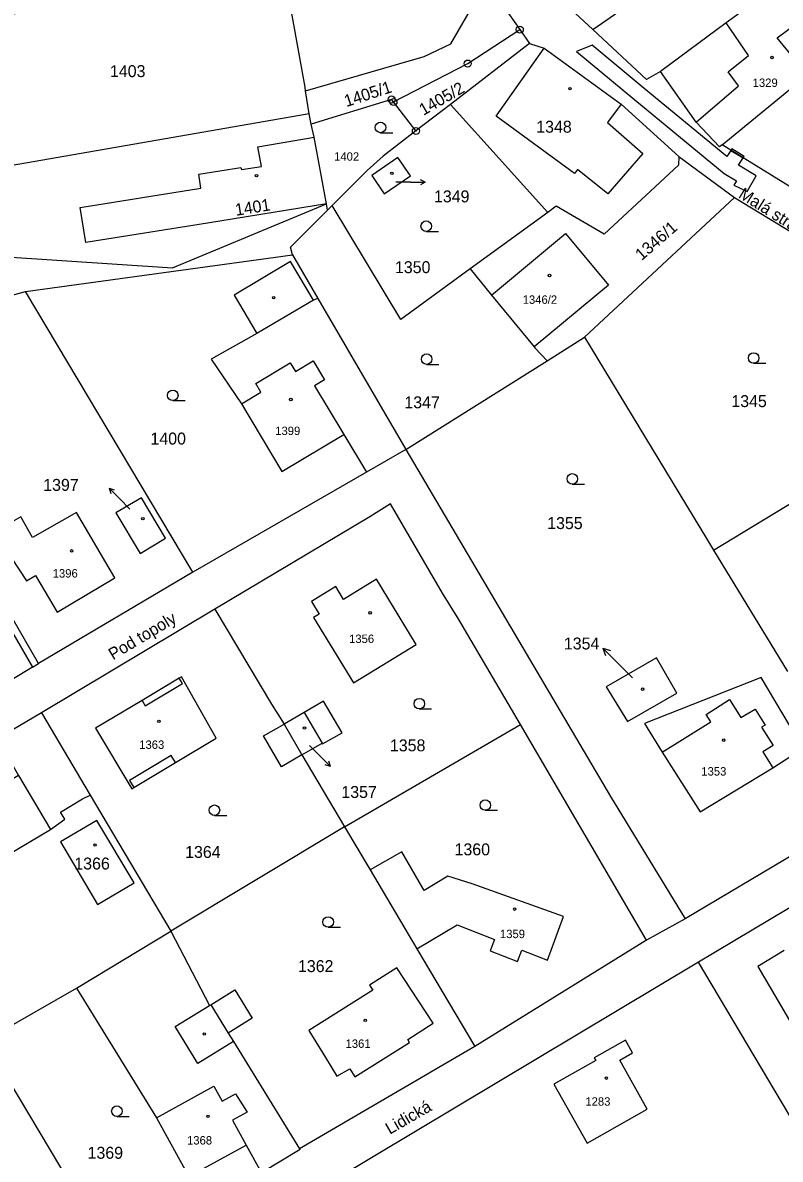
# Model space of a CAD drawing. Extents: x -504988 to -494607, y -1123820 to -1114018.
# Drawn here: x -498111.8 to -498003.8, y -1119261.5 to -1119099.6 of the extents above; entities that cross this region are included whole.
import ezdxf

# ---------------------------------------------------------------- set-up
doc = ezdxf.new("R2010")
doc.units = 0
for name, color, linetype in [('Hranice parcel', 7, 'Continuous'), ('Parcelní čísla', 7, 'Continuous'), ('Pop  PČ popisy', 7, 'Continuous'), ('Vnitřní kresba', 7, 'Continuous'), ('Věcná břemena k části', 7, 'Continuous'), ('Značky bodu BP', 7, 'Continuous'), ('Značky budov', 7, 'Continuous'), ('Značky kultur', 7, 'Continuous')]:
    doc.layers.add(name, color=color, linetype=linetype)

msp = doc.modelspace()

# ---------------------------------------------------------------- linework, layer by layer
at = {"layer": 'Hranice parcel'}
for p, q in [((-498045.7, -1119093.78), (-498040.95, -1119100.58)), ((-498040.95, -1119100.58), (-498039.58, -1119102.55)), ((-498039.58, -1119102.55), (-498050.83, -1119111.22)), ((-498070.95, -1119112.57), (-498071.47, -1119109.28)), ((-498055.76, -1119115.01), (-498058.95, -1119110.88)), ((-498050.83, -1119111.22), (-498055.76, -1119115.01)), ((-498050.83, -1119111.22), (-498036.98, -1119126.61)), ((-498070.66, -1119114.02), (-498070.95, -1119112.57)), ((-497998.68, -1119125.28), (-498012.13, -1119116.99)), ((-498018.31, -1119118.66), (-498010.34, -1119124.5)), ((-498010.34, -1119124.5), (-498031.71, -1119144.39)), ((-498068.34, -1119126.3), (-498068.51, -1119125.4)), ((-498067.67, -1119125.63), (-498068.34, -1119126.3)), ((-498036.98, -1119126.61), (-498048.03, -1119134.66)), ((-498111.4, -1119137.86), (-498073.34, -1119132.64)), ((-498073.34, -1119132.64), (-498069.71, -1119138.88)), ((-498048.03, -1119134.66), (-498044.97, -1119138.39)), ((-498136.33, -1119144.7), (-498111.4, -1119137.86)), ((-498087.55, -1119177.87), (-498111.4, -1119137.86)), ((-498069.71, -1119138.88), (-498057.17, -1119160.39)), ((-498044.97, -1119138.39), (-498038.91, -1119145.75)), ((-498037.03, -1119147.73), (-498031.71, -1119144.39)), ((-498057.17, -1119160.39), (-498037.03, -1119147.73)), ((-498057.17, -1119160.39), (-498062.8, -1119163.63)), ((-498062.8, -1119163.63), (-498087.55, -1119177.87)), ((-498013.33, -1119174.7), (-497996.1, -1119164.22)), ((-498013.33, -1119174.7), (-498002.82, -1119191.98)), ((-498084.4, -1119183.14), (-498109.12, -1119197.88)), ((-498109.12, -1119197.88), (-498115.41, -1119201.58)), ((-498109.12, -1119197.88), (-498102.16, -1119209.6)), ((-498074.54, -1119199.48), (-498071.99, -1119203.88)), ((-498065.91, -1119214.11), (-498040.86, -1119199.56)), ((-498022.92, -1119230.27), (-498040.86, -1119199.56)), ((-498071.99, -1119203.88), (-498065.91, -1119214.11)), ((-497969.63, -1119205.93), (-498015.49, -1119233.41)), ((-498102.16, -1119209.6), (-498090.66, -1119228.96)), ((-497990.95, -1119211.51), (-498017.38, -1119227.24)), ((-498065.91, -1119214.11), (-498090.66, -1119228.96)), ((-498065.91, -1119214.11), (-498062.26, -1119220.26)), ((-498057.77, -1119217.67), (-498062.26, -1119220.26)), ((-498062.26, -1119220.26), (-498055.6, -1119231.5)), ((-498017.38, -1119227.24), (-498022.92, -1119230.27)), ((-498104.11, -1119237.11), (-498090.66, -1119228.96)), ((-498022.92, -1119230.27), (-498047.36, -1119245.4)), ((-498055.6, -1119231.5), (-498047.36, -1119245.4)), ((-498015.49, -1119233.41), (-498067.41, -1119264.46)), ((-498116.93, -1119244.45), (-498104.11, -1119237.11)), ((-498117.19, -1119244.61), (-498098.47, -1119275.83)), ((-498047.36, -1119245.4), (-498072.32, -1119260))]:
    msp.add_line(p, q, dxfattribs=at)
for points in [[(-498030.53, -1119100.54), (-498039.34, -1119092.4), (-498046.56, -1119069.43)], [(-498030.53, -1119100.54), (-498018.03, -1119091.86), (-498003.97, -1119085.2)], [(-498071.47, -1119109.28), (-498071.55, -1119108.79), (-498073.34, -1119098.8), (-498075.74, -1119086.77), (-498132.3, -1119104.31), (-498131.11, -1119113.44)], [(-498071.47, -1119109.28), (-498054.58, -1119104.39), (-498050.79, -1119102.58), (-498045.7, -1119093.78)], [(-498012.13, -1119116.99), (-497999.97, -1119107), (-498004.3, -1119101.73), (-498001.13, -1119099.4), (-498002.9, -1119096.92), (-498003.95, -1119097.55), (-498005.62, -1119095.27), (-498011.54, -1119099.6), (-498020.88, -1119106.56)], [(-498058.95, -1119110.88), (-498048.37, -1119105.41), (-498040.95, -1119100.58)], [(-498020.88, -1119106.56), (-498022.92, -1119107.67), (-498030.53, -1119100.54)], [(-498039.58, -1119102.55), (-498037.48, -1119103.2), (-498026.52, -1119111.17), (-498018.31, -1119118.66)], [(-498012.13, -1119116.99), (-498012.49, -1119117.29), (-498015.82, -1119113.75), (-498020.88, -1119106.56)], [(-498058.95, -1119110.88), (-498059.22, -1119110.53), (-498070.66, -1119114.02)], [(-498070.95, -1119112.57), (-498117.71, -1119120.69), (-498115.44, -1119133.16)], [(-498068.51, -1119125.4), (-498070.27, -1119115.9), (-498070.66, -1119114.02)], [(-498055.76, -1119115.01), (-498060.43, -1119118.6), (-498062.68, -1119120.64), (-498067.67, -1119125.63)], [(-498060.27, -1119123.96), (-498056.53, -1119121.42), (-498058.31, -1119118.81), (-498062.04, -1119121.36), (-498060.27, -1119123.96)], [(-498018.31, -1119118.66), (-498018.36, -1119119.9), (-498028.93, -1119129.72), (-498035.79, -1119125.74), (-498036.98, -1119126.61)], [(-498010.34, -1119124.5), (-497982.64, -1119141.32), (-497971.78, -1119148.38)], [(-498114.09, -1119132.94), (-498090.42, -1119134.5), (-498068.51, -1119125.4)], [(-498073.34, -1119132.64), (-498073.62, -1119131.57), (-498068.34, -1119126.3)], [(-498048.03, -1119134.66), (-498057.89, -1119141.84), (-498067.67, -1119125.63)], [(-498044.97, -1119138.39), (-498034.46, -1119129.61), (-498028.3, -1119136.96), (-498038.91, -1119145.75)], [(-498069.71, -1119138.88), (-498070.35, -1119139.09), (-498073.61, -1119133.62), (-498081.66, -1119138.42), (-498078.41, -1119143.88), (-498084.92, -1119147.52), (-498080.62, -1119153.88), (-498074.84, -1119163.53), (-498066.02, -1119158.25), (-498062.8, -1119163.63)], [(-498087.55, -1119177.87), (-498109.51, -1119190.84), (-498122.93, -1119167.67), (-498136.33, -1119144.7)], [(-498031.71, -1119144.39), (-498014.37, -1119173.04), (-498013.33, -1119174.7)], [(-498137.28, -1119144.99), (-498110.37, -1119191.37), (-498115.64, -1119194.57), (-498135.6, -1119206.51)], [(-498038.91, -1119145.75), (-498038.8, -1119145.89), (-498037.03, -1119147.73)], [(-498057.17, -1119160.39), (-498028.04, -1119209.78), (-498017.38, -1119227.24)], [(-498095.07, -1119175.18), (-498091.44, -1119173.02), (-498094.87, -1119167.25), (-498098.51, -1119169.41), (-498095.07, -1119175.18)], [(-498040.86, -1119199.56), (-498049.65, -1119184.59), (-498051.95, -1119180.83), (-498059.39, -1119168.13), (-498062.3, -1119169.96), (-498084.4, -1119183.14)], [(-498114.25, -1119176.23), (-498113.43, -1119175.76), (-498111.24, -1119179.09), (-498109.97, -1119178.33), (-498106.89, -1119183.53), (-498098.66, -1119178.66), (-498104.13, -1119169.37), (-498110.38, -1119172.93), (-498112.07, -1119169.96), (-498116.41, -1119172.43), (-498114.25, -1119176.23)], [(-498066.07, -1119181.72), (-498067.18, -1119179.91), (-498070.64, -1119182.05), (-498069.55, -1119183.85), (-498070.34, -1119184.33), (-498064.66, -1119193.63), (-498055.7, -1119188.16), (-498061.38, -1119178.86), (-498066.07, -1119181.72)], [(-498084.4, -1119183.14), (-498076.31, -1119196.64), (-498074.54, -1119199.48)], [(-498028.64, -1119194.19), (-498025.6, -1119199.1), (-498018.58, -1119195.08), (-498021.46, -1119190.05), (-498028.64, -1119194.19)], [(-498090.02, -1119204.96), (-498084.23, -1119201.49), (-498089.16, -1119192.78), (-498089.47, -1119192.96), (-498094.78, -1119196.13), (-498101.39, -1119200.07), (-498096.25, -1119208.7), (-498095.95, -1119208.52), (-498090.02, -1119204.96)], [(-498020.66, -1119203.5), (-498015.27, -1119212), (-498004.9, -1119205.7), (-498000.57, -1119202.94), (-498006.55, -1119192.83), (-498023.2, -1119199.42), (-498020.66, -1119203.5)], [(-498071.99, -1119203.88), (-498069.12, -1119202.21), (-498069.05, -1119202.32), (-498066.28, -1119200.71), (-498068.92, -1119196.2), (-498071.68, -1119197.82), (-498074.54, -1119199.48)], [(-498115.41, -1119201.58), (-498112.37, -1119206.82), (-498124.35, -1119213.92), (-498119.8, -1119221.59), (-498107.82, -1119214.5), (-498105.78, -1119213.05), (-498106.4, -1119212.03), (-498103.25, -1119210.13), (-498102.16, -1119209.6)], [(-498101.2, -1119213.23), (-498106.41, -1119216.28), (-498101.14, -1119225.18), (-498095.92, -1119222.09), (-498101.2, -1119213.23)], [(-498051.21, -1119221.14), (-498054.56, -1119223.19), (-498057.77, -1119217.67)], [(-498055.6, -1119231.5), (-498049.9, -1119228.1), (-498044.55, -1119230.18), (-498045.16, -1119231.76), (-498041.27, -1119233.31), (-498040.64, -1119231.69), (-498037.01, -1119233.11), (-498034.71, -1119226.89), (-498047.74, -1119222.24), (-498051.21, -1119221.14)], [(-498090.66, -1119228.96), (-498085.18, -1119239.58), (-498084.97, -1119239.45), (-498082.49, -1119243.5), (-498081.75, -1119244.69), (-498072.32, -1119260)], [(-498003.28, -1119231.73), (-498007.05, -1119234), (-497999.76, -1119246.39), (-497998.25, -1119245.51), (-497995.56, -1119250.06), (-497992, -1119248.03), (-497994.69, -1119243.42), (-497992.88, -1119242.37), (-497993.71, -1119240.91), (-497989.62, -1119238.45), (-497994.74, -1119229.75), (-497996.92, -1119230.9), (-497997.94, -1119228.95), (-497999.45, -1119229.42)], [(-497999.46, -1119260.4), (-498001.57, -1119256.8), (-498015.49, -1119233.41)], [(-498053.32, -1119242.1), (-498058.47, -1119234.19), (-498062.35, -1119236.67)], [(-498062.35, -1119236.67), (-498061.89, -1119237.39), (-498071.03, -1119243.15), (-498068.62, -1119246.99), (-498067, -1119249.65), (-498065.19, -1119248.58), (-498064.46, -1119249.74), (-498056.65, -1119244.82), (-498056.9, -1119244.43), (-498053.32, -1119242.1)], [(-498104.11, -1119237.11), (-498092.72, -1119255.56), (-498088.11, -1119263.94), (-498079.94, -1119259.45), (-498077.76, -1119263.4)], [(-498024.87, -1119246.32), (-498025.89, -1119244.5), (-498030.35, -1119247), (-498030.11, -1119247.42), (-498036.09, -1119250.78), (-498031.36, -1119259.18), (-498022.79, -1119254.35), (-498026.72, -1119247.36), (-498024.87, -1119246.32)], [(-498072.32, -1119260), (-498072.26, -1119260.1), (-498077.76, -1119263.4)]]:
    msp.add_lwpolyline(points, dxfattribs=at)
at = {"layer": 'Pop  PČ popisy'}
for p, q in [((-498054.42, -1119122.32), (-498055.12, -1119121.97)), ((-498056.52, -1119122.32), (-498058.62, -1119122.32)), ((-498056.52, -1119122.32), (-498054.42, -1119122.32)), ((-498054.42, -1119122.32), (-498055.12, -1119122.67)), ((-498097.99, -1119167.37), (-498099.48, -1119165.89)), ((-498099.48, -1119165.89), (-498098.73, -1119166.13)), ((-498099.48, -1119165.89), (-498099.23, -1119166.63)), ((-498096.51, -1119168.86), (-498097.99, -1119167.37)), ((-498026.99, -1119190.79), (-498029.11, -1119188.67)), ((-498029.11, -1119188.67), (-498028.05, -1119189.02)), ((-498029.11, -1119188.67), (-498028.76, -1119189.73)), ((-498024.87, -1119192.92), (-498026.99, -1119190.79)), ((-498070.91, -1119202.56), (-498069.42, -1119204.04)), ((-498069.42, -1119204.04), (-498067.93, -1119205.53)), ((-498067.93, -1119205.53), (-498068.68, -1119205.28)), ((-498067.93, -1119205.53), (-498068.18, -1119204.78))]:
    msp.add_line(p, q, dxfattribs=at)
at = {"layer": 'Vnitřní kresba'}
for p, q in [((-498008.35, -1119104.26), (-498011.54, -1119099.6)), ((-498044.32, -1119112.91), (-498037.48, -1119103.2)), ((-498011.28, -1119106.61), (-498008.35, -1119104.26)), ((-498009.78, -1119108.6), (-498011.28, -1119106.61)), ((-498015.82, -1119113.75), (-498009.78, -1119108.6)), ((-498026.52, -1119111.17), (-498028.44, -1119113.81)), ((-498033.15, -1119121.06), (-498044.32, -1119112.91)), ((-498028.44, -1119113.81), (-498023.41, -1119118.2)), ((-498078.28, -1119117.29), (-498070.27, -1119115.9)), ((-498077.78, -1119120.06), (-498078.28, -1119117.29)), ((-498023.41, -1119118.2), (-498028.41, -1119123.96)), ((-498086.71, -1119121.15), (-498080.68, -1119120.22)), ((-498080.68, -1119120.22), (-498080.63, -1119120.5)), ((-498080.63, -1119120.5), (-498077.78, -1119120.06)), ((-498086.4, -1119123.14), (-498086.71, -1119121.15)), ((-498032.74, -1119120.51), (-498033.15, -1119121.06)), ((-498028.41, -1119123.96), (-498032.74, -1119120.51)), ((-498103.58, -1119125.91), (-498086.4, -1119123.14)), ((-498102.77, -1119130.91), (-498103.58, -1119125.91)), ((-498068.51, -1119125.4), (-498085.44, -1119128.13)), ((-498085.44, -1119128.13), (-498102.77, -1119130.91)), ((-498070.35, -1119139.09), (-498078.41, -1119143.88)), ((-498072.91, -1119149.27), (-498070.39, -1119147.76)), ((-498070.39, -1119147.76), (-498068.78, -1119150.45)), ((-498078.58, -1119150.98), (-498073.65, -1119148.03)), ((-498073.65, -1119148.03), (-498072.91, -1119149.27)), ((-498077.84, -1119152.22), (-498078.58, -1119150.98)), ((-498068.78, -1119150.45), (-498070.19, -1119151.29)), ((-498080.62, -1119153.88), (-498077.84, -1119152.22)), ((-498070.19, -1119151.29), (-498066.02, -1119158.25)), ((-498110.37, -1119191.37), (-498109.51, -1119190.84)), ((-498089.01, -1119193.73), (-498089.47, -1119192.96)), ((-498094.32, -1119196.9), (-498089.01, -1119193.73)), ((-498094.78, -1119196.13), (-498094.32, -1119196.9)), ((-498014.41, -1119198.1), (-498011.05, -1119196)), ((-498011.05, -1119196), (-498009.44, -1119198.57)), ((-498071.68, -1119197.82), (-498069.12, -1119202.21)), ((-498013.75, -1119199.16), (-498014.41, -1119198.1)), ((-498009.44, -1119198.57), (-498007.41, -1119197.36)), ((-498007.41, -1119197.36), (-498006.01, -1119199.65)), ((-498077.45, -1119201.17), (-498074.54, -1119199.48)), ((-498020.66, -1119203.5), (-498013.75, -1119199.16)), ((-498006.01, -1119199.65), (-498006.49, -1119199.93)), ((-498074.9, -1119205.57), (-498077.45, -1119201.17)), ((-498006.49, -1119199.93), (-498004.84, -1119202.56)), ((-498004.84, -1119202.56), (-498006.33, -1119203.45)), ((-498090.62, -1119203.96), (-498096.55, -1119207.51)), ((-498090.02, -1119204.96), (-498090.62, -1119203.96)), ((-498071.99, -1119203.88), (-498074.9, -1119205.57)), ((-498006.33, -1119203.45), (-498004.9, -1119205.7)), ((-498112.37, -1119206.82), (-498107.82, -1119214.5)), ((-498096.55, -1119207.51), (-498095.95, -1119208.52)), ((-498084.97, -1119239.45), (-498081.55, -1119237.35)), ((-498081.55, -1119237.35), (-498079.07, -1119241.38)), ((-498090.05, -1119242.57), (-498085.18, -1119239.58)), ((-498079.07, -1119241.38), (-498082.49, -1119243.5)), ((-498086.83, -1119247.81), (-498090.05, -1119242.57)), ((-498081.75, -1119244.69), (-498086.83, -1119247.81)), ((-498092.72, -1119255.56), (-498084.55, -1119251.07)), ((-498084.55, -1119251.07), (-498083.38, -1119253.2)), ((-498083.38, -1119253.2), (-498081.48, -1119252.15)), ((-498081.48, -1119252.15), (-498079.81, -1119254.77)), ((-498079.81, -1119254.77), (-498081.88, -1119255.91)), ((-498081.88, -1119255.91), (-498079.94, -1119259.45))]:
    msp.add_line(p, q, dxfattribs=at)
at = {"layer": 'Věcná břemena k části'}
for points in [[(-498024.54, -1119110.59), (-498011.81, -1119121.06), (-498010.09, -1119122.12), (-498010.43, -1119122.75), (-498008.54, -1119123.63), (-498007.28, -1119121.39), (-498009.78, -1119119.86), (-498009.14, -1119118.84), (-498010.87, -1119117.77), (-498011.43, -1119118.67), (-498023.22, -1119108.97), (-498030.62, -1119102.81), (-498032.85, -1119103.67)], [(-498010.87, -1119117.77), (-498009.14, -1119118.84), (-498009, -1119118.63), (-498010.73, -1119117.55)]]:
    msp.add_lwpolyline(points, close=True, dxfattribs=at)
at = {"layer": 'Značky bodu BP'}
for centre, radius in [((-498040.95, -1119100.58), 0.5), ((-498040.95, -1119100.58), 0.0303), ((-498048.37, -1119105.41), 0.5), ((-498048.37, -1119105.41), 0.0303), ((-498059.22, -1119110.53), 0.5), ((-498058.95, -1119110.88), 0.5), ((-498059.22, -1119110.53), 0.0303), ((-498058.95, -1119110.88), 0.0303), ((-498055.76, -1119115.01), 0.5), ((-498055.76, -1119115.01), 0.0303)]:
    msp.add_circle(centre, radius, dxfattribs=at)
at = {"layer": 'Značky budov'}
for centre in [(-498005.03, -1119104.55), (-498033.79, -1119108.98), (-498078.47, -1119121.38), (-498059.18, -1119121.05), (-498036.72, -1119135.6), (-498076.01, -1119138.75), (-498073.58, -1119153.26), (-498094.67, -1119170.24), (-498104.81, -1119174.82), (-498062.28, -1119183.64), (-498023.45, -1119194.51), (-498092.38, -1119199.09), (-498071.63, -1119200.05), (-498011.89, -1119201.78), (-498101.47, -1119216.72), (-498041.69, -1119225.84), (-498062.98, -1119241.67), (-498085.91, -1119243.63), (-498028.61, -1119249.91), (-498085.37, -1119255.34)]:
    msp.add_circle(centre, 0.175, dxfattribs=at)
at = {"layer": 'Značky kultur'}
for p, q in [((-498060.8, -1119115.26), (-498059.05, -1119115.26)), ((-498054.28, -1119129.32), (-498052.53, -1119129.32)), ((-498054.22, -1119148.26), (-498052.47, -1119148.26)), ((-498007.63, -1119148.09), (-498005.88, -1119148.09)), ((-498090.4, -1119153.42), (-498088.65, -1119153.42)), ((-498033.47, -1119165.31), (-498031.72, -1119165.31)), ((-498055.27, -1119197.33), (-498053.52, -1119197.33)), ((-498084.46, -1119212.51), (-498082.71, -1119212.51)), ((-498045.87, -1119211.77), (-498044.12, -1119211.77)), ((-498068.26, -1119228.43), (-498066.51, -1119228.43)), ((-498098.36, -1119255.37), (-498096.61, -1119255.37))]:
    msp.add_line(p, q, dxfattribs=at)
for centre in [(-498060.8, -1119114.51), (-498054.28, -1119128.57), (-498054.22, -1119147.51), (-498007.63, -1119147.34), (-498090.4, -1119152.67), (-498033.47, -1119164.56), (-498055.27, -1119196.58), (-498084.46, -1119211.76), (-498045.87, -1119211.02), (-498068.26, -1119227.68), (-498098.36, -1119254.62)]:
    msp.add_circle(centre, 0.75, dxfattribs=at)

# ---------------------------------------------------------------- texts
at = {"layer": 'Parcelní čísla'}
for s, height, p in [('1403', 1.7, (-498099.35, -1119107.34)), ('1329', 1.2, (-498007.77, -1119108.74)), ('1348', 1.7, (-498038.61, -1119115.26)), ('1402', 1.2, (-498067.41, -1119119.25)), ('1349', 1.7, (-498053.18, -1119125.18)), ('1350', 1.7, (-498058.74, -1119135.26)), ('1346/2', 1.2, (-498040.54, -1119139.63)), ('1347', 1.7, (-498057.4, -1119154.51)), ('1345', 1.7, (-498010.81, -1119154.34)), ('1399', 1.2, (-498075.8, -1119158.32)), ('1400', 1.7, (-498093.58, -1119159.67)), ('1397', 1.7, (-498108.86, -1119166.27)), ('1355', 1.7, (-498037.05, -1119171.71)), ('1396', 1.2, (-498107.51, -1119178.62)), ('1356', 1.2, (-498065.28, -1119187.94)), ('1354', 1.7, (-498034.67, -1119188.86)), ('1363', 1.2, (-498095.18, -1119203.02)), ('1358', 1.7, (-498059.46, -1119203.37)), ('1353', 1.2, (-498015.09, -1119206.82)), ('1357', 1.7, (-498066.38, -1119210.01)), ('1364', 1.7, (-498088.64, -1119218.55)), ('1360', 1.7, (-498050.25, -1119218.18)), ('1366', 1.7, (-498104.43, -1119220.2)), ('1359', 1.2, (-498043.78, -1119229.97)), ('1362', 1.7, (-498072.56, -1119234.81)), ('1361', 1.2, (-498065.78, -1119245.6)), ('1283', 1.2, (-498031.61, -1119253.84)), ('1369', 1.7, (-498102.54, -1119261.4)), ('1368', 1.2, (-498088.37, -1119259.37))]:
    msp.add_text(s, height=height, dxfattribs=at).set_placement(p)
for s, rotation, p in [('1405/1', 18, (-498065.66, -1119111.61)), ('1405/2', 30, (-498054.69, -1119112.87)), ('1401', 9, (-498081.39, -1119127.1)), ('1346/1', 41, (-498023.6, -1119133.55))]:
    msp.add_text(s, height=1.7, rotation=rotation, dxfattribs=at).set_placement(p)
at = {"layer": 'Pop  PČ popisy'}
for s, rotation, p in [('Malá strana', 328, (-498009.92, -1119124.42)), ('Pod topoly', 31, (-498098.91, -1119190.42)), ('Lidická', 30, (-498059.48, -1119257.99))]:
    msp.add_text(s, height=1.7, rotation=rotation, dxfattribs=at).set_placement(p)

doc.saveas('drawing.dxf')
